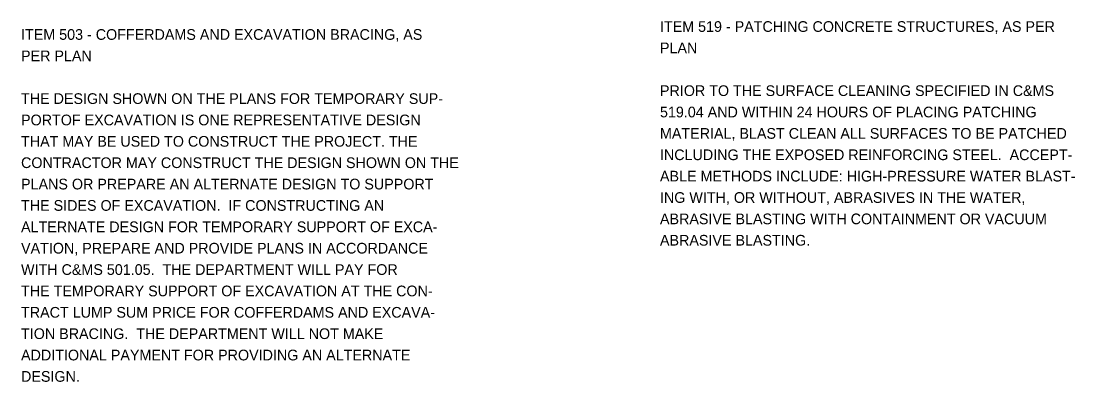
# Model space of a CAD drawing. Extents: x -11.4 to 50.8, y -16 to 31.7.
# Drawn here: x 5.91 to 19.7, y -15.98 to -11.25 of the extents above; entities that cross this region are included whole.
import ezdxf

# ---------------------------------------------------------------- set-up
doc = ezdxf.new("R2010")
doc.units = 0
doc.layers.add('SH_Text', color=7, linetype='Continuous')

msp = doc.modelspace()

# ---------------------------------------------------------------- texts
at = {"layer": 'SH_Text'}
for s, p in [('ITEM 519 - PATCHING CONCRETE STRUCTURES, AS PER', (14.271, -11.39)), ('ITEM 503 - COFFERDAMS AND EXCAVATION BRACING, AS', (5.907, -11.494)), ('PLAN', (14.271, -11.67)), ('PER PLAN', (5.907, -11.774)), ('PRIOR TO THE SURFACE CLEANING SPECIFIED IN C&MS', (14.271, -12.23)), ('THE DESIGN SHOWN ON THE PLANS FOR TEMPORARY SUP-', (5.907, -12.334)), ('519.04 AND WITHIN 24 HOURS OF PLACING PATCHING', (14.271, -12.51)), ('PORTOF EXCAVATION IS ONE REPRESENTATIVE DESIGN', (5.907, -12.614)), ('MATERIAL, BLAST CLEAN ALL SURFACES TO BE PATCHED', (14.271, -12.79)), ('THAT MAY BE USED TO CONSTRUCT THE PROJECT. THE', (5.907, -12.894)), ('INCLUDING THE EXPOSED REINFORCING STEEL.  ACCEPT-', (14.271, -13.07)), ('CONTRACTOR MAY CONSTRUCT THE DESIGN SHOWN ON THE', (5.907, -13.174)), ('ABLE METHODS INCLUDE: HIGH-PRESSURE WATER BLAST-', (14.271, -13.35)), ('PLANS OR PREPARE AN ALTERNATE DESIGN TO SUPPORT', (5.907, -13.454)), ('ING WITH, OR WITHOUT, ABRASIVES IN THE WATER,', (14.271, -13.63)), ('THE SIDES OF EXCAVATION.  IF CONSTRUCTING AN', (5.907, -13.734)), ('ABRASIVE BLASTING WITH CONTAINMENT OR VACUUM', (14.271, -13.91)), ('ALTERNATE DESIGN FOR TEMPORARY SUPPORT OF EXCA-', (5.907, -14.014)), ('ABRASIVE BLASTING.', (14.271, -14.19)), ('VATION, PREPARE AND PROVIDE PLANS IN ACCORDANCE', (5.907, -14.294)), ('WITH C&MS 501.05.  THE DEPARTMENT WILL PAY FOR', (5.907, -14.574)), ('THE TEMPORARY SUPPORT OF EXCAVATION AT THE CON-', (5.907, -14.854)), ('TRACT LUMP SUM PRICE FOR COFFERDAMS AND EXCAVA-', (5.907, -15.134)), ('TION BRACING.  THE DEPARTMENT WILL NOT MAKE', (5.907, -15.414)), ('ADDITIONAL PAYMENT FOR PROVIDING AN ALTERNATE', (5.907, -15.694)), ('DESIGN.', (5.907, -15.974))]:
    msp.add_text(s, height=0.14, dxfattribs=at).set_placement(p)

doc.saveas('drawing.dxf')
